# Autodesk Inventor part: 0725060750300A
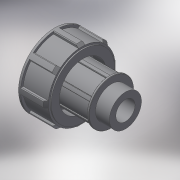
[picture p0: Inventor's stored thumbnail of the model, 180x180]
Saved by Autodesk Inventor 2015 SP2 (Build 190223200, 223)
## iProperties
Created: 2017-04
Part Number: 0725060750300A
Material: Generic
Description: PLASSON THREADED ADAPTOR 75-3"
Document SubType Name: Modeling
Designer: KIM
Density: 1 g/cm^3
Appearance: Default
Author: KIM
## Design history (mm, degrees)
derived "07250.ipt"
feature "Solid1::07250.ipt"
tag "TaggingFeature1"
body "Solid1"
other parameters: "d1" = 87.884, "d2" = 137, "d3" = 33, "d6" = 134, "d7" = 124.62, "d8" = 107.2, "d9" = 75, "d10" = 96.6724, "d12" = 52.7304, "d13" = 61.5188, "d14" = 37.95, "d15" = 100.5, "d16" = 4.11, "d17" = 54.8, "d18" = 33, "d19" = 39.6, "d24" = 17.5768, "d25" = 8.7884, "d27" = 0, "d28" = 7.03072, "d31" = 1.75768, "d35" = 360 deg, "d41" = 29.337, "d56" = 82.5, "d57" = 7.5, "d58" = 3.75, "d60" = 0, "d61" = 0.87884, "d64" = 0.87884, "d68" = 360 deg, "d_" = 75, "R_" = 87.884, "E_" = 134, "H_" = 137, "l_2" = 33, "d55" = 75
